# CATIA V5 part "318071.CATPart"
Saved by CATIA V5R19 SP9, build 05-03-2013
Part number: 318071
Source: Unknown
Bounding box of the stored display mesh (mm): x -147.762 to 15, y 107.861 to 128.446, z 477.184 to 504.918
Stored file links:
  D:\16-SIL\kale oto\R19_V1\318071.CATPart
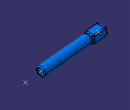
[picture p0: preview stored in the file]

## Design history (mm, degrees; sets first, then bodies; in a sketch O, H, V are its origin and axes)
Set1
  Point1 to Point3: stored without definition
Body1 "241\\236\\234\\MANIFOLD_SOLID_BREP #161559" (main body)
  Solid1: solid without history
